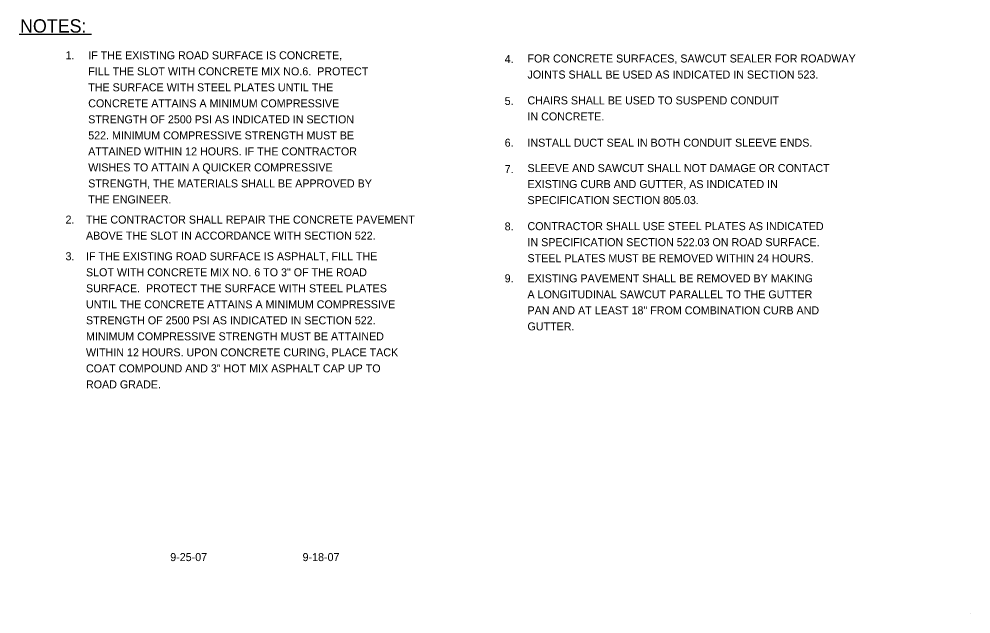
# Model space of a CAD drawing. Extents: x -234.3 to -227.16, y 225.75 to 234.94.
# Drawn here: x -234.3 to -227.16, y 225.75 to 230.21 of the extents above; entities that cross this region are included whole.
import ezdxf

# ---------------------------------------------------------------- set-up
doc = ezdxf.new("R2010")
doc.units = 0
for name, color, linetype in [('Default', 7, 'Continuous'), ('DETL-NOTE', 7, 'Continuous'), ('TTLB-TEXT', 7, 'Continuous')]:
    doc.layers.add(name, color=color, linetype=linetype)

msp = doc.modelspace()

# ---------------------------------------------------------------- linework, layer by layer
at = {"layer": 'DETL-NOTE'}
msp.add_line((-234.2986, 230.0988), (-233.7547, 230.0988), dxfattribs=at)
at = {"layer": 'TTLB-TEXT'}
msp.add_line((-227.1625, 225.7545), (-227.1625, 225.7545), dxfattribs=at)

# ---------------------------------------------------------------- texts
at = {"layer": 'Default'}
for s, p in [('9-25-07', (-233.1652, 226.1505)), ('9-18-07', (-232.173, 226.1505))]:
    msp.add_text(s, height=0.06, dxfattribs=at).set_placement(p)
at = {"layer": 'DETL-NOTE'}
for s, height, p in [('NOTES:', 0.1, (-234.291, 230.11)), ('1. ', 0.06, (-233.95, 229.91)), ('IF THE EXISTING ROAD SURFACE IS CONCRETE,', 0.06, (-233.78, 229.91)), ('4. ', 0.06, (-230.658, 229.882)), ('FOR CONCRETE SURFACES, SAWCUT SEALER FOR ROADWAY', 0.06, (-230.487, 229.886)), ('FILL THE SLOT WITH CONCRETE MIX NO.6.  PROTECT ', 0.06, (-233.78, 229.79)), ('JOINTS SHALL BE USED AS INDICATED IN SECTION 523.', 0.06, (-230.487, 229.766)), ('THE SURFACE WITH STEEL PLATES UNTIL THE', 0.06, (-233.78, 229.67)), ('CONCRETE ATTAINS A MINIMUM COMPRESSIVE', 0.06, (-233.78, 229.55)), ('5. ', 0.06, (-230.658, 229.568)), ('CHAIRS SHALL BE USED TO SUSPEND CONDUIT ', 0.06, (-230.487, 229.572)), ('IN CONCRETE.', 0.06, (-230.487, 229.452)), ('STRENGTH OF 2500 PSI AS INDICATED IN SECTION ', 0.06, (-233.78, 229.43)), ('522. MINIMUM COMPRESSIVE STRENGTH MUST BE ', 0.06, (-233.78, 229.31)), ('6. ', 0.06, (-230.658, 229.255)), ('INSTALL DUCT SEAL IN BOTH CONDUIT SLEEVE ENDS.', 0.06, (-230.487, 229.255)), ('ATTAINED WITHIN 12 HOURS. IF THE CONTRACTOR ', 0.06, (-233.78, 229.19)), ('WISHES TO ATTAIN A QUICKER COMPRESSIVE ', 0.06, (-233.78, 229.07)), ('7. ', 0.06, (-230.658, 229.057)), ('SLEEVE AND SAWCUT SHALL NOT DAMAGE OR CONTACT', 0.06, (-230.487, 229.065)), ('STRENGTH, THE MATERIALS SHALL BE APPROVED BY ', 0.06, (-233.78, 228.95)), ('EXISTING CURB AND GUTTER, AS INDICATED IN', 0.06, (-230.487, 228.945)), ('THE ENGINEER.', 0.06, (-233.78, 228.83)), ('SPECIFICATION SECTION 805.03.', 0.06, (-230.487, 228.825)), ('2. ', 0.06, (-233.95, 228.679)), ('THE CONTRACTOR SHALL REPAIR THE CONCRETE PAVEMENT', 0.06, (-233.7967, 228.679)), ('8. ', 0.06, (-230.658, 228.628)), ('CONTRACTOR SHALL USE STEEL PLATES AS INDICATED', 0.06, (-230.487, 228.6299)), ('ABOVE THE SLOT IN ACCORDANCE WITH SECTION 522.', 0.06, (-233.7967, 228.559)), ('IN SPECIFICATION SECTION 522.03 ON ROAD SURFACE.', 0.06, (-230.487, 228.5099)), ('3. ', 0.06, (-233.95, 228.4043)), ('IF THE EXISTING ROAD SURFACE IS ASPHALT, FILL THE', 0.06, (-233.7967, 228.4043)), ('STEEL PLATES MUST BE REMOVED WITHIN 24 HOURS.', 0.06, (-230.487, 228.3899)), ('SLOT WITH CONCRETE MIX NO. 6 TO 3" OF THE ROAD ', 0.06, (-233.7967, 228.2843)), ('9. ', 0.06, (-230.658, 228.239)), ('EXISTING PAVEMENT SHALL BE REMOVED BY MAKING', 0.06, (-230.487, 228.239)), ('SURFACE.  PROTECT THE SURFACE WITH STEEL PLATES', 0.06, (-233.7967, 228.1643)), ('A LONGITUDINAL SAWCUT PARALLEL TO THE GUTTER', 0.06, (-230.487, 228.119)), ('UNTIL THE CONCRETE ATTAINS A MINIMUM COMPRESSIVE ', 0.06, (-233.7967, 228.0443)), ('PAN AND AT LEAST 18" FROM COMBINATION CURB AND ', 0.06, (-230.487, 227.999)), ('STRENGTH OF 2500 PSI AS INDICATED IN SECTION 522. ', 0.06, (-233.7967, 227.9243)), ('GUTTER.', 0.06, (-230.487, 227.879)), ('MINIMUM COMPRESSIVE STRENGTH MUST BE ATTAINED ', 0.06, (-233.7967, 227.8043)), ('WITHIN 12 HOURS. UPON CONCRETE CURING, PLACE TACK ', 0.06, (-233.7967, 227.6843)), ('COAT COMPOUND AND 3" HOT MIX ASPHALT CAP UP TO ', 0.06, (-233.7967, 227.5643)), ('ROAD GRADE.', 0.06, (-233.7967, 227.4443))]:
    msp.add_text(s, height=height, dxfattribs=at).set_placement(p)

doc.saveas('drawing.dxf')
